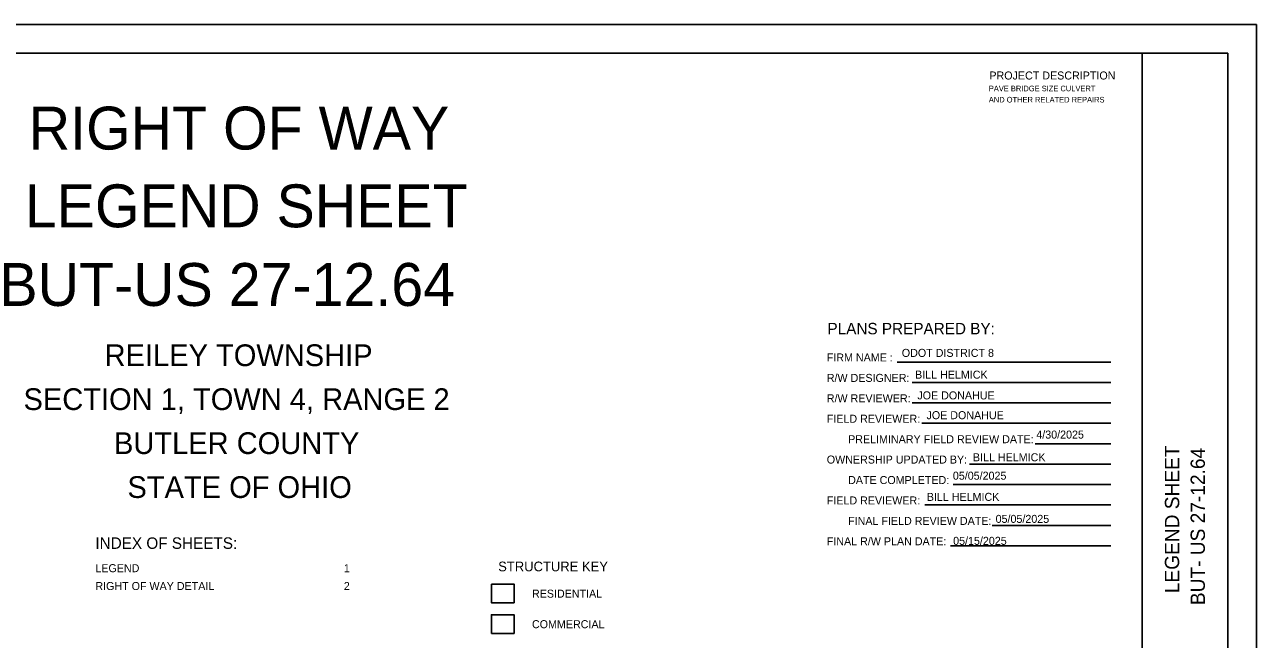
# Model space of a CAD drawing. Extents: x 0 to 34, y 0 to 22.
# Drawn here: x 12.45 to 34, y 11.25 to 22 of the extents above; entities that cross this region are included whole.
import ezdxf

# ---------------------------------------------------------------- set-up
doc = ezdxf.new("R2010")
doc.units = 0
for name, color, linetype in [('SC_Shading1', 7, 'Continuous'), ('SH_Border', 7, 'Continuous'), ('SH_Cut_Line', 7, 'Continuous'), ('SH_Data', 7, 'Continuous'), ('SH_Text', 7, 'Continuous')]:
    doc.layers.add(name, color=color, linetype=linetype)

msp = doc.modelspace()

# ---------------------------------------------------------------- linework, layer by layer
at = {"layer": 'SC_Shading1'}
msp.add_lwpolyline([(20.62, 11.357), (21.017, 11.357), (21.017, 11.683), (20.62, 11.683)], close=True, dxfattribs=at)
at = {"layer": 'SH_Border'}
msp.add_line((32, 0.5), (32, 21.5), dxfattribs=at)
msp.add_lwpolyline([(1.5, 21.5), (33.5, 21.5), (33.5, 0.5), (1.5, 0.5)], close=True, dxfattribs=at)
at = {"layer": 'SH_Cut_Line'}
msp.add_lwpolyline([(0, 0), (34, 0), (34, 22), (0, 22)], close=True, dxfattribs=at)
at = {"layer": 'SH_Text'}
for p, q in [((27.718, 16.101), (31.455, 16.101)), ((27.982, 15.744), (31.455, 15.744)), ((27.982, 15.387), (31.455, 15.387)), ((28.147, 15.03), (31.455, 15.03)), ((30.128, 14.672), (31.455, 14.672)), ((28.983, 14.316), (31.455, 14.316)), ((28.697, 13.958), (31.455, 13.958)), ((28.2, 13.602), (31.455, 13.602)), ((29.381, 13.244), (31.455, 13.244)), ((28.652, 12.887), (31.455, 12.887))]:
    msp.add_line(p, q, dxfattribs=at)
msp.add_lwpolyline([(20.62, 12.219), (21.017, 12.219), (21.017, 11.893), (20.62, 11.893)], close=True, dxfattribs=at)

# ---------------------------------------------------------------- texts
at = {"layer": 'SH_Data'}
for s, height, p in [('RIGHT OF WAY', 0.75, (12.527, 19.816)), ('LEGEND SHEET', 0.75, (12.458, 18.457)), ('BUT-US 27-12.64', 0.75, (12.013, 17.082)), ('REILEY TOWNSHIP', 0.38, (13.854, 16.03)), ('SECTION 1, TOWN 4, RANGE 2', 0.38, (12.435, 15.262)), ('BUTLER COUNTY', 0.38, (14.018, 14.493)), ('STATE OF OHIO', 0.38, (14.253, 13.725)), ('INDEX OF SHEETS:', 0.2, (13.692, 12.835)), ('LEGEND                             ', 0.14, (13.692, 12.427)), ('1     ', 0.14, (18.038, 12.427)), ('RIGHT OF WAY DETAIL                ', 0.14, (13.692, 12.115)), ('2     ', 0.14, (18.038, 12.115))]:
    msp.add_text(s, height=height, dxfattribs=at).set_placement(p)
for s, p in [('LEGEND SHEET', (32.65, 12.06)), ('BUT- US 27-12.64', (33.1, 11.851))]:
    msp.add_text(s, height=0.25, rotation=90, dxfattribs=at).set_placement(p)
at = {"layer": 'SH_Text'}
for s, height, p in [('PROJECT DESCRIPTION', 0.14, (29.33, 21.041)), ('PAVE BRIDGE SIZE CULVERT', 0.098, (29.32, 20.835)), ('AND OTHER RELATED REPAIRS', 0.098, (29.32, 20.639)), ('PLANS PREPARED BY:', 0.2, (26.498, 16.586)), ('FIRM NAME :', 0.14, (26.486, 16.111)), ('ODOT DISTRICT 8', 0.14, (27.798, 16.191)), ('BILL HELMICK', 0.14, (28.03, 15.811)), ('R/W DESIGNER:', 0.14, (26.486, 15.754)), ('R/W REVIEWER:', 0.14, (26.486, 15.397)), ('JOE DONAHUE', 0.14, (28.07, 15.448)), ('FIELD REVIEWER:', 0.14, (26.486, 15.04)), ('JOE DONAHUE', 0.14, (28.23, 15.102)), ('4/30/2025', 0.14, (30.151, 14.763)), ('PRELIMINARY FIELD REVIEW DATE:', 0.14, (26.859, 14.682)), ('OWNERSHIP UPDATED BY:', 0.14, (26.486, 14.326)), ('BILL HELMICK', 0.14, (29.042, 14.366)), ('DATE COMPLETED:', 0.14, (26.859, 13.968)), ('05/05/2025', 0.14, (28.691, 14.044)), ('BILL HELMICK', 0.14, (28.235, 13.674)), ('FIELD REVIEWER:', 0.14, (26.486, 13.611)), ('FINAL FIELD REVIEW DATE:', 0.14, (26.859, 13.254)), ('05/05/2025', 0.14, (29.439, 13.289)), ('FINAL R/W PLAN DATE:', 0.14, (26.486, 12.897)), ('05/15/2025', 0.14, (28.696, 12.905)), ('STRUCTURE KEY', 0.17, (20.738, 12.442)), ('RESIDENTIAL', 0.14, (21.329, 11.982)), ('COMMERCIAL', 0.14, (21.329, 11.448))]:
    msp.add_text(s, height=height, dxfattribs=at).set_placement(p)

doc.saveas('drawing.dxf')
